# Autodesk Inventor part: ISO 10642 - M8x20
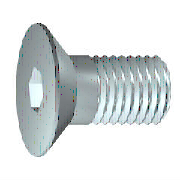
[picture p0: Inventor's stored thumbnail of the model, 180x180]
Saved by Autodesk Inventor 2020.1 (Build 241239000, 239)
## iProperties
Created: 2019-01
Part Number: ISO 10642 - M8x20
Material: Stahl, weich
Description: Senkschrauben mit Innensechskant
Document SubType Name: Modeling
Standard: ISO 10642
Designer: lutzd
Standards Organization: ISO
Language: de-DE
Size Designation: M8x20
Categories: <MemberInstance><Categories><Category DisplayName="Verbindungselemente" InternalName="e4da775c-781d-43d5-af7c-5136215cf5a6" Mnemonic="FSTN"><Category DisplayNam
Mass: 9.83932 g
Surface Area: 9.27162 cm^2
Volume: 1.25342 cm^3
Density: 7.85 g/cm^3
Appearance: Halbpoliert
IsCustomPart: 0
Author: lutzd
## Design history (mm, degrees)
node "WorkPoint1"
sketch "Skizze2"
  geometry: L1 (-4, -20)-(0, -20); L2 (-4, -4.4)-(-4, -20); L3 (-8, -0.4)-(-4, -4.4); L4 (-8, 0)-(-8, -0.4); L5 (0, 0)-(-8, 0); L6 (0, -20)-(0, 0); L7 (0, -20)-(0, 0); L8 (0, -24)-(0, 4) reference; L9 (1.6, 0)-(-9.6, 0) reference
  constraints: 14 end point, 3 vertical, 2 horizontal
  dimensions: "d3" = 8 distance of L5.start L4.start (= 0.5 x dk); "d5" = 4 distance of L1.start L1.end (= 0.5 x NND); "d7" = 20 distance of L1.end L5.start (= NLG); "ParC" = 0.4 distance of L4.start L3.start; "d22" = 0 distance between parallel lines of L8 L6; "d23" = 0 distance between parallel lines of L9 L5; "d43" = 45 deg angle of L6 L3 (= 0.5 x ang)
revolve "Drehung1" stored, may be unused: angle "d8" = 360 deg
node "MSC_A1"
node "MSC_PF1"
node "MSC_PT1"
body "Solid1"
node "Skizze1"
sketch "Skizze3"
  geometry: L1 (-2.5, 1.443)-(-2.5, -1.443); L2 (0, 2.887)-(-2.5, 1.443); L3 (2.5, 1.443)-(0, 2.887); L4 (2.5, -1.443)-(2.5, 1.443); L5 (0, -2.887)-(2.5, -1.443); L6 (-2.5, -1.443)-(0, -2.887); C1 r 2.5 at (0, 0); C2 r 4 at (0, 0) reference
  constraints: 12 end point, 6 tangent, 2 parallel, 2 vertical, 1 centre point, 1 concentric
  dimensions: "d11" = 5 diameter of C1 (= ParS); "d13" = 120 deg angle of L1 L2; "d15" = 120 deg angle of L6 L1
extrude "Extrusion1" cut sketch "Skizze3" distance "d16" = 3.5 (= ParT); taper "d17" = 0 deg
fillet "Rundung1" dims "d18" = 0.5 (= r)
chamfer "Fase1" distance "d19" = 0.625 (= 0.5 x PTC); stored, may be unused: angle "d20" = 45 deg, second distance "d39" = 0.625 (= 0.5 x PTC)
feature "Gewinde1" dims "d35" = 0, "b" = 13.1
other parameters: "NND" = 8 [user parameter; used in 2 equation terms], "PTC" = 1.25 [user parameter; used in 2 equation terms], "dk" = 16 [user parameter; used in 1 equation term], "ParK" = 4.4 [user parameter], "ParS" = 5 [user parameter; used in 1 equation term], "ParT" = 3.5 [user parameter; used in 1 equation term], "r" = 0.5 [user parameter; used in 1 equation term], "NLG" = 20 [user parameter; used in 1 equation term], "d0" = 45 deg (derived), "d2" = 3 (derived), "d4" = 1.5 (derived), "d6" = 8 (derived), "d9" = 0, "d10" = 2 (derived), "d12" = 120 deg (derived), "d14" = 120 deg (derived), "d37" = 0, "d38" = 0, "d40" = 0, "d41" = 0, "d42" = 0, "ang" = 90 deg [user parameter; used in 1 equation term], "THREADDIA" = 8 (= NND) [user parameter]
